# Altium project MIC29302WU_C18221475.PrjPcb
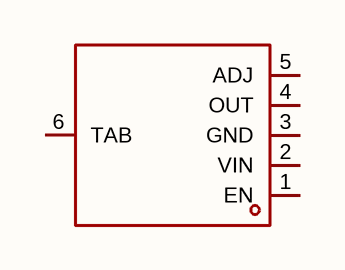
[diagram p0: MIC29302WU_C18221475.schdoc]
1 sheet, 1 parts. Net scope: global (net labels, ports and power ports of the same name join across sheets).

## Sheet MIC29302WU_C18221475.schdoc
size 127 x 101 mm

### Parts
U?  mic29302wu_c18221475  [TO-263-5_L10.3-W8.9-P1.70-LS15.2-BR]  (value not drawn)

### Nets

Not connected (* = marked no-connect by the designer): U? 1(EN) 2(VIN) 3(GND) 4(OUT) 5(ADJ) 6(TAB)

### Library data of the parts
U? = mic29302wu_c18221475: 输出极性:正极;工作电压:26V;输出电压:-;输出电流:3A;电源纹波抑制比(PSRR):-;输出类型:可调;; Manufacturer: TECH PUBLIC(台舟); AddInBom: yes; ModelId: 4a8fbd1e513247a6876ffa3074266da2; ModelTransform: 600.15514,409.448,0,0,0,0,-43.621,0.001,0; Output Configuration: 正极; Voltage - Supply: 26V; Output Current: 3A; Voltage Dropout: 370mV@(3A); standby current: 37mA; Noise: 400uVrms；260uVrms; Output Type: 可调; Number of Outputs: 1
